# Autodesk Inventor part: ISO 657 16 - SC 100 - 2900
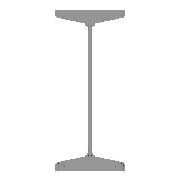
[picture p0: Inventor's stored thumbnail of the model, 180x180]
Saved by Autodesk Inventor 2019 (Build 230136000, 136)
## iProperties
_CCFamilyMember: 1
_CCFamilyDisplayName: ISO 657/16 - 1980 - Poutres en acier laminées à chaud - Partie 16: profilés en H (série métrique) - Cotes et propriétés de section
_FrameMemberDoc: Frame Member File
_Version: 15.0.0
_GetPNFromCC: 1
Created: 2018-07
Part Number: ISO 657 16 - SC 100 - 2900
Material: Acier, doux
Description: Poutres en acier laminées à chaud - Partie 16: profilés en H (série métrique) - Cotes et propriétés de section
Document SubType Name: Modeling
Standard: ISO
Designer: Fabian Perrée
Standard Revision: First edition 1980-02-15
Standards Organization: ISO
Language: fr-FR
Size Designation: SC 100
Categories: <MemberInstance><Categories><Category DisplayName="Profilés" InternalName="089c4875-fa83-4c05-b084-43b9cc11f5ed" Mnemonic="GRDR"><CategoryParameter DisplayName=
Stock Number: SC 100
Density: 7.85 g/cm^3
Appearance: Semi-poli
Mass: 57968.8 g
Surface Area: 15748.4 cm^2
Volume: 7384.56 cm^3
IsCustomPart: 1
G_W: 100,000 mm
G_H: 100,000 mm
+457F8912-0A6F-456F-8C90-B17ED96C1981+DETAILDECOUPE1: Angle de coupe 90,00 deg
G_L: 2900,000 mm
Author: Fabian Perrée
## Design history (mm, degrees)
node "Plan de départ"
node "Plan de fin"
sketch "Esquisse"
  geometry: L1 (-3, 0)-(-3, -26.266); L2 (-13.33, -38.149)-(-44.835, -42.577); L3 (-50, -48.518)-(-50, -50); L4 (-50, -50)-(0, -50); L5 (-26.5, -50)-(-26.5, -40); L6 (-61.333, 0)-(81.777, 0); L7 (0, 0)-(0, -50); L8 (0, -60)-(0, 80); L9 (3, 0)-(3, -26.266); L10 (13.33, -38.149)-(44.835, -42.577); L11 (50, -48.518)-(50, -50); L12 (50, -50)-(0, -50); L13 (-3, 0)-(0, 0); L14 (-3, 0)-(-3, 26.266); L15 (-13.33, 38.149)-(-44.835, 42.577); L16 (-50, 48.518)-(-50, 50); L17 (-50, 50)-(0, 50); L18 (50, 48.518)-(50, 50); L19 (13.33, 38.149)-(44.835, 42.577); L20 (3, 0)-(3, 26.266); L21 (50, 50)-(0, 50); L22 (0, 108)-(0, -88) reference; L23 (-89.955, 0)-(110.399, 0) reference; A1 r 6 centre (-44, 48.518) between (-50, 48.518) and (-44.835, 42.577); A2 r 6 centre (44, 48.518) between (44.835, 42.577) and (50, 48.518); A3 r 6 centre (44, -48.518) between (50, -48.518) and (44.835, -42.577); A4 r 6 centre (-44, -48.518) between (-44.835, -42.577) and (-50, -48.518); A5 r 12 centre (-15, 26.266) between (-3, 26.266) and (-13.33, 38.149); A6 r 12 centre (15, 26.266) between (13.33, 38.149) and (3, 26.266); A7 r 12 centre (15, -26.266) between (3, -26.266) and (13.33, -38.149); A8 r 12 centre (-15, -26.266) between (-13.33, -38.149) and (-3, -26.266); 14 further points
  constraints: 42 end point, 24 point on line, 17 symmetric about line, 16 point on circle, 16 tangent, 8 centre point, 6 equal radius, 4 collinear, 2 perpendicular, 12 other
  dimensions: "d1" = 10 vertical distance of L3.end L5.end (= G_T1); "d2" = 23.5 distance between parallel lines of L5 L3 (= -0.25 x G_T + 0.25 x G_W); "d3" = 3 distance between parallel lines of L1 L7 (= 0.5 x G_T); "d4" = 50 distance between parallel lines of L7 L3 (= 0.5 x G_W); "d9" = 50 distance from line of L1.start L4 (= 0.5 x G_H); "d14" = 98 deg angle of L2 L1 (= G_NG); "d15" = 6 radius of A1 (= G_ER); "d16" = 12 radius of A5 (= G_IR)
extrude "Corps" new body sketch "Esquisse" stored distance "d5" = 2900 (= G_L); taper "d6" = 0 deg
node "Driven Length"
  sketch "Sketch3"
    geometry: L1 (0, 0)-(10, 0) reference
    constraints: 2 end point, 1 horizontal
  workplane "Work Plane3"
  sketch "Sketch4"
    geometry: L1 (-2, 100)-(12, 100) reference; L2 (-2, 3000)-(12, 3000) reference
    dimensions: "d20" = 2900 distance between parallel lines of L1 L2 (derived)
node "Plan de construction4"
feature "Scission1"
body "Solid1"
other parameters: "G_W" = 100 (= G_H) [user parameter; used in 2 equation terms], "G_H" = 100 [user parameter; used in 2 equation terms], "G_T" = 6 [user parameter; used in 2 equation terms], "G_T1" = 10 [user parameter; used in 1 equation term], "G_L" = 2900 (= d20) [user parameter; used in 1 equation term], "G_ER" = 6 [user parameter; used in 1 equation term], "G_IR" = 12 [user parameter; used in 1 equation term], "G_NG" = 98 deg [user parameter; used in 1 equation term], "G_OFFSET_END" = 0 [user parameter; used in 1 equation term], "d19" = 90 deg
